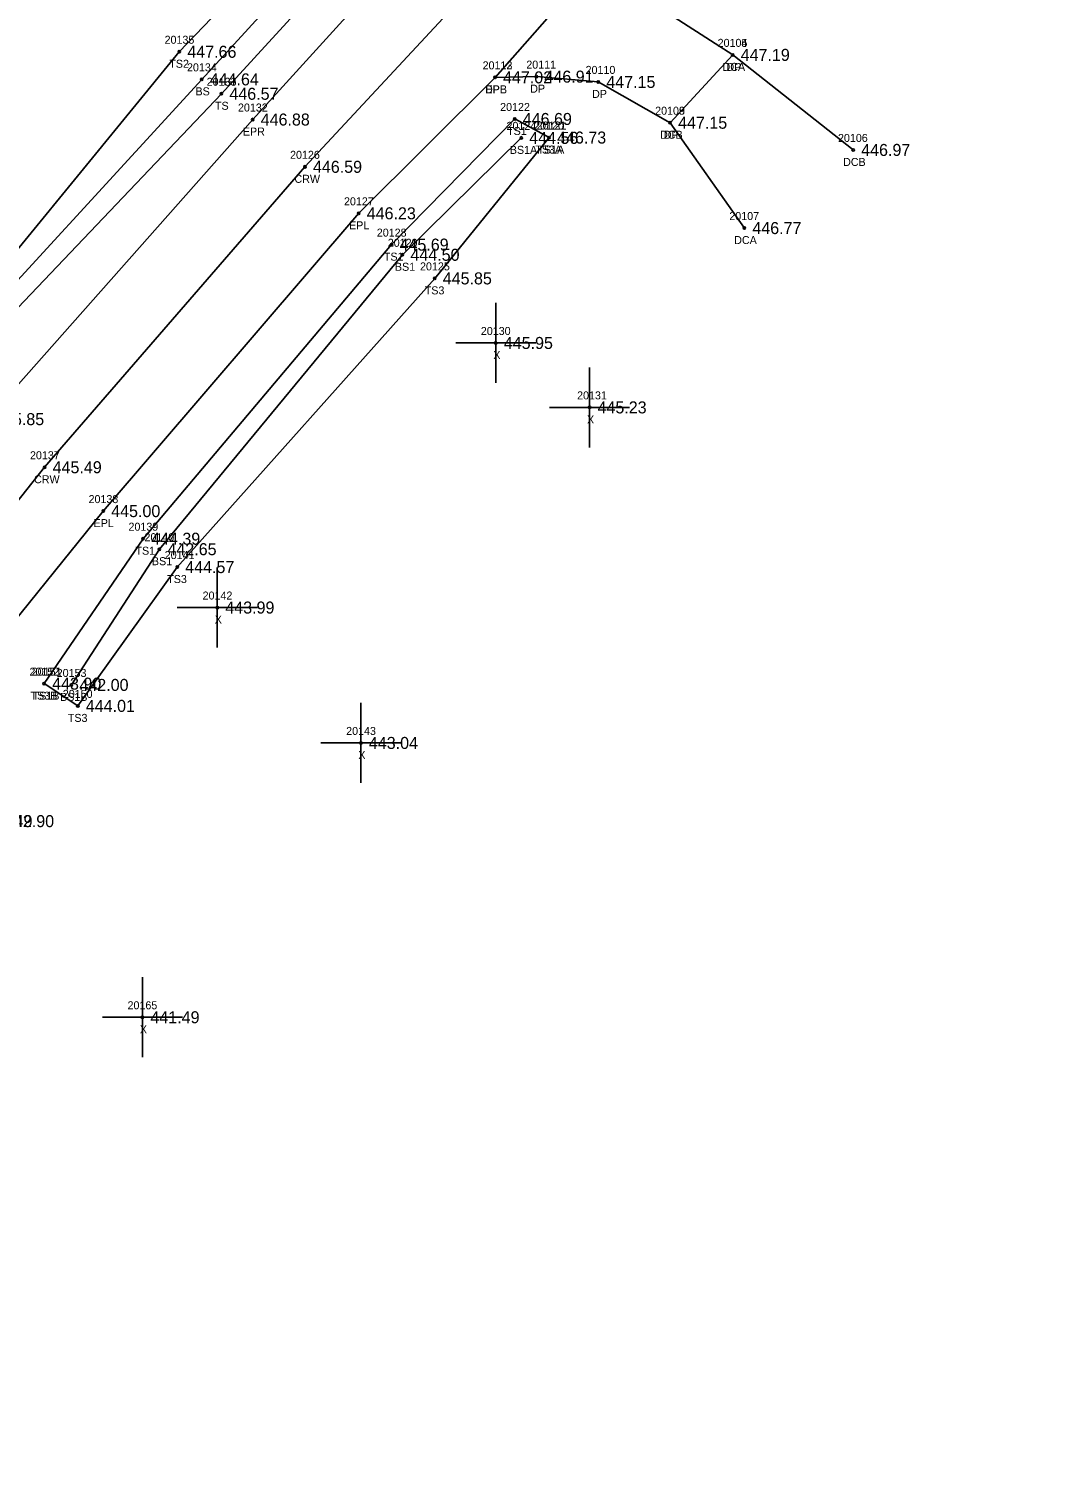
# Model space of a CAD drawing. Extents: x 1763022 to 1764007, y 824123 to 825394.
# Drawn here: x 1763579.5 to 1763705.9, y 824827.2 to 825006.9 of the extents above; entities that cross this region are included whole.
import ezdxf

# ---------------------------------------------------------------- set-up
doc = ezdxf.new("R2010")
doc.units = 0
for name, color, linetype in [('RD_DTM_BkLn1', 7, 'Continuous'), ('RD_DTM_BkLn2', 7, 'Continuous'), ('RD_DTM_BkLn_txCode', 7, 'Continuous'), ('RD_EX_Conc', 7, 'Continuous'), ('RD_EX_Conc_txCode', 7, 'Continuous'), ('RD_EX_Driveway', 7, 'Continuous'), ('RD_EX_Driveway_txCode', 7, 'Continuous'), ('RD_EX_Misc', 7, 'Continuous'), ('RD_EX_Misc_txCode', 7, 'Continuous'), ('RD_EX_Road', 7, 'Continuous'), ('RD_EX_Road_txCode', 7, 'Continuous'), ('RD_EX_TX_Conc_ELEV', 7, 'Continuous'), ('RD_EX_TX_Driveway_ELEV', 7, 'Continuous'), ('RD_EX_TX_Misc_ELEV', 7, 'Continuous'), ('RD_EX_TX_Road_ELEV', 7, 'Continuous'), ('RD_HC_Survey_ELEV', 7, 'Continuous'), ('RD_HC_Survey_txCode', 7, 'Continuous'), ('RD_SMD_Locator', 7, 'Continuous')]:
    doc.layers.add(name, color=color, linetype=linetype)

msp = doc.modelspace()

# ---------------------------------------------------------------- linework, layer by layer
at = {"layer": 'RD_DTM_BkLn1'}
msp.add_lwpolyline([(1763957.85, 825358.99), (1763889.22, 825284.86), (1763820.79, 825210.5), (1763751.37, 825137.44), (1763682.52, 825063.34), (1763613.99, 824989.62), (1763581.46, 824952.08), (1763550.2, 824912.66), (1763519.29, 824872.78), (1763491.16, 824832.15)], dxfattribs=at)
at = {"layer": 'RD_DTM_BkLn2'}
for points in [[(1763745.88, 825160.71), (1763743.95, 825161.45), (1763741.33, 825161.23), (1763734.19, 825151.51), (1763667.93, 825076.53), (1763598.29, 825004), (1763566.28, 824964.92), (1763532.04, 824927.7), (1763520.45, 824914.1), (1763512.76, 824909.25), (1763510.52, 824906.49), (1763509.94, 824903.93)], [(1763745.88, 825160.71), (1763746.84, 825156.51), (1763744.4, 825153.55), (1763739.17, 825147.71), (1763672.03, 825073.56), (1763603.55, 824998.75), (1763569.03, 824962.49), (1763535.77, 824923.77), (1763524.58, 824910.39), (1763517.67, 824903.1), (1763511.98, 824902.34), (1763509.94, 824903.93)], [(1763743.62, 825158.44), (1763736.6, 825149.65), (1763669.73, 825075.6), (1763601.09, 825000.55), (1763567.43, 824963.88), (1763533.82, 824926.24), (1763521.76, 824912.79), (1763514.73, 824907.04), (1763512.63, 824905.46)], [(1763644.5, 824993.28), (1763640.21, 824995.6), (1763624.81, 824979.9), (1763593.77, 824943.15), (1763581.4, 824925.04)], [(1763644.5, 824993.28), (1763630.21, 824975.68), (1763598.03, 824939.61), (1763585.61, 824922.26), (1763581.4, 824925.04)], [(1763641.02, 824993.24), (1763626.17, 824978.63), (1763595.81, 824941.84), (1763584.81, 824924.88)]]:
    msp.add_lwpolyline(points, dxfattribs=at)
at = {"layer": 'RD_EX_Conc'}
for p, q in [((1763667.44, 825003.61), (1763682.5, 824991.73)), ((1763668.9, 824981.97), (1763659.62, 824995.13))]:
    msp.add_line(p, q, dxfattribs=at)
at = {"layer": 'RD_EX_Driveway'}
msp.add_lwpolyline([(1763653.53, 825018.75), (1763654.2, 825013.82), (1763657.9, 825009.73), (1763667.44, 825003.61), (1763659.62, 824995.13), (1763650.65, 825000.23), (1763642.92, 825000.89), (1763637.74, 825000.8)], dxfattribs=at)
at = {"layer": 'RD_EX_Misc'}
for p, q in [((1763637.84, 824962.61), (1763637.84, 824972.61)), ((1763632.84, 824967.61), (1763642.84, 824967.61)), ((1763649.55, 824954.56), (1763649.55, 824964.56)), ((1763644.55, 824959.56), (1763654.55, 824959.56)), ((1763603.04, 824929.55), (1763603.04, 824939.55)), ((1763598.04, 824934.55), (1763608.04, 824934.55)), ((1763620.98, 824912.63), (1763620.98, 824922.63)), ((1763615.98, 824917.63), (1763625.98, 824917.63)), ((1763593.68, 824878.35), (1763593.68, 824888.35)), ((1763588.68, 824883.35), (1763598.68, 824883.35))]:
    msp.add_line(p, q, dxfattribs=at)
at = {"layer": 'RD_EX_Road'}
for points in [[(1763951.03, 825365.44), (1763882.12, 825291.59), (1763813.3, 825217.44), (1763784.22, 825184.64), (1763754.38, 825152.48), (1763744.67, 825142.84), (1763675.27, 825070.17), (1763607.46, 824995.53), (1763574.27, 824958.09), (1763542.37, 824919.2), (1763512.11, 824877.96), (1763483.2, 824837.35)], [(1763963.89, 825353.59), (1763895.68, 825279.08), (1763827.34, 825205.22), (1763758.38, 825131.33), (1763689.43, 825057.33), (1763653.53, 825018.75), (1763637.74, 825000.8), (1763620.71, 824983.81), (1763588.78, 824946.6), (1763557.13, 824907.38), (1763526.52, 824867.67), (1763498.43, 824827.25)]]:
    msp.add_lwpolyline(points, dxfattribs=at)
at = {"layer": 'RD_SMD_Locator'}
for centre in [(1763598.29, 825004), (1763667.44, 825003.61), (1763667.44, 825003.61), (1763601.09, 825000.55), (1763637.74, 825000.8), (1763637.74, 825000.8), (1763642.92, 825000.89), (1763650.65, 825000.23), (1763603.55, 824998.75), (1763607.46, 824995.53), (1763640.21, 824995.6), (1763659.62, 824995.13), (1763659.62, 824995.13), (1763641.02, 824993.24), (1763644.5, 824993.28), (1763644.5, 824993.28), (1763682.5, 824991.73), (1763613.99, 824989.62), (1763620.71, 824983.81), (1763668.9, 824981.97), (1763624.81, 824979.9), (1763626.17, 824978.63), (1763630.21, 824975.68), (1763637.84, 824967.61), (1763649.55, 824959.56), (1763581.46, 824952.08), (1763588.78, 824946.6), (1763593.77, 824943.15), (1763595.81, 824941.84), (1763598.03, 824939.61), (1763603.04, 824934.55), (1763581.4, 824925.04), (1763581.4, 824925.04), (1763584.81, 824924.88), (1763585.61, 824922.26), (1763620.98, 824917.63), (1763593.68, 824883.35)]:
    msp.add_circle(centre, 0.15, dxfattribs=at)

# ---------------------------------------------------------------- texts
at = {"layer": 'RD_DTM_BkLn_txCode'}
for s, p in [('20135', (1763596.45, 825005)), ('TS2', (1763597.04, 825002)), ('20134', (1763599.25, 825001.55)), ('BS', (1763600.31, 824998.55)), ('20133', (1763601.71, 824999.75)), ('TS', (1763602.75, 824996.75)), ('20122', (1763638.38, 824996.6)), ('20124', (1763639.18, 824994.24)), ('TS1', (1763639.25, 824993.6)), ('20120', (1763642.63, 824994.28)), ('20121', (1763642.95, 824994.28)), ('BS1A', (1763639.59, 824991.24)), ('TS3A', (1763642.77, 824991.28)), ('TS1A', (1763643.05, 824991.28)), ('20128', (1763622.97, 824980.9)), ('20129', (1763624.34, 824979.63)), ('TS1', (1763623.85, 824977.9)), ('BS1', (1763625.23, 824976.63)), ('20125', (1763628.37, 824976.68)), ('TS3', (1763628.96, 824973.68)), ('20139', (1763591.94, 824944.15)), ('20140', (1763593.94, 824942.84)), ('TS1', (1763592.81, 824941.15)), ('BS1', (1763594.87, 824939.84)), ('20141', (1763596.47, 824940.61)), ('TS3', (1763596.78, 824937.61)), ('20152', (1763579.57, 824926.04)), ('20151', (1763579.85, 824926.04)), ('20153', (1763582.97, 824925.88)), ('TS3B', (1763579.69, 824923.04)), ('TS1B', (1763579.97, 824923.04)), ('20150', (1763583.73, 824923.26)), ('BS1B', (1763583.39, 824922.88)), ('TS3', (1763584.36, 824920.26))]:
    msp.add_text(s, height=1, dxfattribs=at).set_placement(p)
at = {"layer": 'RD_EX_Conc_txCode'}
for s, p in [('20105', (1763665.56, 825004.61)), ('DCA', (1763666.17, 825001.61)), ('20108', (1763657.75, 824996.13)), ('DCB', (1763658.37, 824993.13)), ('20106', (1763680.6, 824992.73)), ('DCB', (1763681.24, 824989.73)), ('20107', (1763667.02, 824982.97)), ('DCA', (1763667.63, 824979.97))]:
    msp.add_text(s, height=1, dxfattribs=at).set_placement(p)
at = {"layer": 'RD_EX_Driveway_txCode'}
for s, p in [('20104', (1763665.56, 825004.61)), ('20112', (1763636.19, 825001.8)), ('20111', (1763641.65, 825001.89)), ('20110', (1763649.06, 825001.23)), ('DP', (1763666.66, 825001.61)), ('DPB', (1763636.49, 824998.8)), ('DP', (1763642.14, 824998.89)), ('DP', (1763649.87, 824998.23)), ('20109', (1763657.75, 824996.13)), ('DP', (1763658.84, 824993.13))]:
    msp.add_text(s, height=1, dxfattribs=at).set_placement(p)
at = {"layer": 'RD_EX_Misc_txCode'}
for s, p in [('20130', (1763635.97, 824968.61)), ('X', (1763637.53, 824965.61)), ('20131', (1763648, 824960.56)), ('X', (1763649.24, 824957.56)), ('20142', (1763601.2, 824935.55)), ('X', (1763602.72, 824932.55)), ('20143', (1763619.14, 824918.63)), ('X', (1763620.66, 824915.63)), ('20165', (1763591.82, 824884.35)), ('X', (1763593.36, 824881.35))]:
    msp.add_text(s, height=1, dxfattribs=at).set_placement(p)
at = {"layer": 'RD_EX_Road_txCode'}
for s, p in [('20113', (1763636.19, 825001.8)), ('EPL', (1763636.54, 824998.8)), ('20132', (1763605.62, 824996.53)), ('EPR', (1763606.23, 824993.53)), ('20127', (1763618.87, 824984.81)), ('EPL', (1763619.5, 824981.81)), ('20138', (1763586.95, 824947.6)), ('EPL', (1763587.58, 824944.6))]:
    msp.add_text(s, height=1, dxfattribs=at).set_placement(p)
at = {"layer": 'RD_EX_TX_Conc_ELEV'}
for s, p in [('447.19', (1763668.44, 825002.86)), ('447.15', (1763660.62, 824994.38)), ('446.97', (1763683.5, 824990.98)), ('446.77', (1763669.9, 824981.22))]:
    msp.add_text(s, height=1.5, dxfattribs=at).set_placement(p)
at = {"layer": 'RD_EX_TX_Driveway_ELEV'}
for s, p in [('447.19', (1763668.44, 825002.86)), ('447.02', (1763638.74, 825000.05)), ('446.91', (1763643.92, 825000.14)), ('447.15', (1763651.65, 824999.48)), ('447.15', (1763660.62, 824994.38))]:
    msp.add_text(s, height=1.5, dxfattribs=at).set_placement(p)
at = {"layer": 'RD_EX_TX_Misc_ELEV'}
for s, p in [('447.66', (1763599.29, 825003.25)), ('444.64', (1763602.09, 824999.8)), ('446.57', (1763604.55, 824998)), ('446.69', (1763641.21, 824994.85)), ('444.56', (1763642.02, 824992.49)), ('446.73', (1763645.5, 824992.53)), ('446.73', (1763645.5, 824992.53)), ('445.69', (1763625.81, 824979.15)), ('444.50', (1763627.17, 824977.88)), ('445.85', (1763631.21, 824974.93)), ('445.95', (1763638.84, 824966.86)), ('445.23', (1763650.55, 824958.81)), ('444.39', (1763594.77, 824942.4)), ('442.65', (1763596.81, 824941.09)), ('444.57', (1763599.03, 824938.86)), ('443.99', (1763604.04, 824933.8)), ('443.90', (1763582.4, 824924.29)), ('443.90', (1763582.4, 824924.29)), ('442.00', (1763585.81, 824924.13)), ('444.01', (1763586.61, 824921.51)), ('443.04', (1763621.98, 824916.88)), ('441.49', (1763573.81, 824907.11)), ('442.90', (1763576.51, 824907.11)), ('441.49', (1763594.68, 824882.6))]:
    msp.add_text(s, height=1.5, dxfattribs=at).set_placement(p)
at = {"layer": 'RD_EX_TX_Road_ELEV'}
for s, p in [('447.02', (1763638.74, 825000.05)), ('446.88', (1763608.46, 824994.78)), ('446.23', (1763621.71, 824983.06)), ('445.85', (1763575.27, 824957.34)), ('445.00', (1763589.78, 824945.85))]:
    msp.add_text(s, height=1.5, dxfattribs=at).set_placement(p)
at = {"layer": 'RD_HC_Survey_ELEV'}
for s, p in [('446.59', (1763614.99, 824988.87)), ('445.49', (1763582.46, 824951.33))]:
    msp.add_text(s, height=1.5, dxfattribs=at).set_placement(p)
at = {"layer": 'RD_HC_Survey_txCode'}
for s, p in [('20126', (1763612.13, 824990.62)), ('CRW', (1763612.68, 824987.62)), ('20137', (1763579.63, 824953.08)), ('CRW', (1763580.14, 824950.08))]:
    msp.add_text(s, height=1, dxfattribs=at).set_placement(p)

doc.saveas('drawing.dxf')
